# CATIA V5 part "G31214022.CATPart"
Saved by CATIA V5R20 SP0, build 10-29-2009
Part number: G31214022
Revision: 9
Definition: design
Nomenclature: G31214022
Source: made
Description: NOT SPECIFIED
Bounding box of the stored display mesh (mm): x -6 to 22, y -12.31 to 12.31, z -12.5 to 12.5
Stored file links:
  C:\Users\Raffaele\Desktop\3D X SITO CF\BOLEX\23-BUSH REF 312\G31214022.CATPart

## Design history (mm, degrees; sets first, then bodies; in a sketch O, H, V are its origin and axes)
Body1 "MANIFOLD_SOLID_BREP #5541" (main body)
  Solid1: solid without history
Body2 "MANIFOLD_SOLID_BREP #5684"
  Solid2: solid without history
Body3 "MANIFOLD_SOLID_BREP #5827"
  Solid3: solid without history
Body4 "MANIFOLD_SOLID_BREP #5970"
  Solid4: solid without history
Body5 "MANIFOLD_SOLID_BREP #6113"
  Solid5: solid without history
Body6 "MANIFOLD_SOLID_BREP #6256"
  Solid6: solid without history
Body7 "MANIFOLD_SOLID_BREP #6399"
  Solid7: solid without history
Body8 "MANIFOLD_SOLID_BREP #6544"
  Solid8: solid without history
Body9 "MANIFOLD_SOLID_BREP #6689"
  Solid9: solid without history
Body10 "MANIFOLD_SOLID_BREP #6834"
  Solid10: solid without history
Body11 "MANIFOLD_SOLID_BREP #6979"
  Solid11: solid without history
Body12 "MANIFOLD_SOLID_BREP #7122"
  Solid12: solid without history
Body13 "MANIFOLD_SOLID_BREP #7265"
  Solid13: solid without history
Body14 "MANIFOLD_SOLID_BREP #7410"
  Solid14: solid without history
Body15 "MANIFOLD_SOLID_BREP #7555"
  Solid15: solid without history
Body16 "MANIFOLD_SOLID_BREP #7700"
  Solid16: solid without history
Body17 "MANIFOLD_SOLID_BREP #7845"
  Solid17: solid without history
Body18 "MANIFOLD_SOLID_BREP #7990"
  Solid18: solid without history
Body19 "MANIFOLD_SOLID_BREP #8135"
  Solid19: solid without history
Body20 "MANIFOLD_SOLID_BREP #8280"
  Solid20: solid without history
Body21 "MANIFOLD_SOLID_BREP #8425"
  Solid21: solid without history
Body22 "MANIFOLD_SOLID_BREP #8570"
  Solid22: solid without history
Body23 "MANIFOLD_SOLID_BREP #8715"
  Solid23: solid without history
Body24 "MANIFOLD_SOLID_BREP #8860"
  Solid24: solid without history
Body25 "MANIFOLD_SOLID_BREP #9005"
  Solid25: solid without history
Body26 "MANIFOLD_SOLID_BREP #9148"
  Solid26: solid without history
Body27 "MANIFOLD_SOLID_BREP #9293"
  Solid27: solid without history
Body28 "MANIFOLD_SOLID_BREP #9438"
  Solid28: solid without history
Body29 "MANIFOLD_SOLID_BREP #9581"
  Solid29: solid without history
Body30 "MANIFOLD_SOLID_BREP #9726"
  Solid30: solid without history
Body31 "MANIFOLD_SOLID_BREP #9871"
  Solid31: solid without history
Body32 "MANIFOLD_SOLID_BREP #10014"
  Solid32: solid without history
Body33 "MANIFOLD_SOLID_BREP #10157"
  Solid33: solid without history
Body34 "MANIFOLD_SOLID_BREP #10302"
  Solid34: solid without history
Body35 "MANIFOLD_SOLID_BREP #10447"
  Solid35: solid without history
Body36 "MANIFOLD_SOLID_BREP #10592"
  Solid36: solid without history
Body37 "MANIFOLD_SOLID_BREP #10737"
  Solid37: solid without history
Body38 "MANIFOLD_SOLID_BREP #10882"
  Solid38: solid without history
Body39 "MANIFOLD_SOLID_BREP #11027"
  Solid39: solid without history
Body40 "MANIFOLD_SOLID_BREP #11172"
  Solid40: solid without history
Body41 "MANIFOLD_SOLID_BREP #11317"
  Solid41: solid without history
